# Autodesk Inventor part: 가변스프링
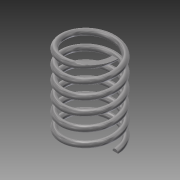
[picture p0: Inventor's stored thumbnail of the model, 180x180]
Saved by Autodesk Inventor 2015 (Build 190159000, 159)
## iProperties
Created: 2015-10
Part Number: 가변스프링
Material: Steel, Mild
Document SubType Name: Modeling
Designer: youjin08
Density: 7.85 g/cm^3
Appearance: Semi-Polished
Mass: 128.878 g
Surface Area: 133.051 cm^2
Volume: 16.4176 cm^3
Author: youjin08
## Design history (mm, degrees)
sketch "Sketch1"
  geometry: L1 (0, 0)-(-22.5, 0); L2 (-22.5, 0)-(-22.5, 73.25); L3 (-22.5, 73.25)-(0, 73.25); L4 (0, 73.25)-(0, 0); C1 r 2.5 at (-22.5, 0)
  constraints: 8 end point, 2 parallel, 1 centre point, 1 coincident, 1 horizontal, 1 perpendicular
  dimensions: "d0" = 73.25 distance between parallel lines of L1 L3 (derived); "d1" = 45 diameter of L2 L4; "d2" = 5 diameter of C1
coil "Coil1" sketch "Sketch1" pitch "d3" = 10; turns "d5" = 6; dims "d4" = 73.25 (= d0), "d6" = 0, angle "d7" = 90 deg, angle "d8" = 90 deg, "d9" = 0, "d10" = 0
sketch "Sketch2"
  geometry: L1 (25, 0)-(20, 0) reference; 1 further point
  constraints: 1 horizontal alignment
extrude "Extrusion1" cut sketch "Sketch2" stored distance "d11" = 10; taper "d12" = 0 deg
workplane "Work Plane1"
sketch "Sketch3"
  geometry: L1 (20, 0)-(25, 0) reference; 1 further point
  constraints: 1 horizontal alignment
extrude "Extrusion2" cut sketch "Sketch3" stored distance "d14" = 10; taper "d15" = 0 deg
body "Solid1"
node "Project Cut Edges1"
node "Project Cut Edges2"
other parameters: "d13" = 73.25 (= d0)
